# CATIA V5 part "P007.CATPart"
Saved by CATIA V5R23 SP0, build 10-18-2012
Part number: P007
Definition: Vis HC M5x10.1
Description: Vis ISO10642 F HC M5x10.1
Bounding box of the stored display mesh (mm): x -10.29 to 0, y -5.598 to 5.598, z -5.598 to 5.598
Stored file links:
  C:\wamp\www\COURS\CONCEPTION GMP1\TITRE 02-SEMESTRE 2\03-TP7-PRESSE MECANIQUE\eleve\P007.CATPart
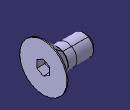
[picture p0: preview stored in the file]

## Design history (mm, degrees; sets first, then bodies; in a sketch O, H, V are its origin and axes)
Parameters
  Material = "St"
  d_dia_max = 5 mm
  l_length_nom = 10 mm
  b_ref = 22
  l_length_min = 9.71 mm
  l_length_max = 10.29 mm
  dk_head_dia_max = 11.2 mm
  dk_head_dia_min = 9.43 mm
  ls = 5.5 mm
  k_hed_depth = 3.1 mm
  r = 0.2 mm
  s_across_flats = 3 mm
  t_insert_depth = 1.9 mm
  P_pitch = 0.8 mm
  PartNumber = "Vis ISO10642 F HC M5x10"
Body1 "PartBody" (main body)
  Sketch1 on zx-plane, origin (0, 0, 0), H (-1, 0, 0), V (0, 0, 1)
    line L1 (0, 5.6) -> (0.2667, 5.6)
    point P2 (0.2667, 5.6)
    line L2 (0.2667, 5.6) -> (3.3667, 2.5)
    line L3 (3.3667, 2.5) -> (5.5, 2.5)
    line L4 (5.5, 2.5) -> (5.5, 2.439)
    point P5 (5.5, 2.439)
    line L5 (5.5, 2.439) -> (9.49, 2.439)
    point P6 (9.49, 2.439)
    line L6 (9.49, 2.439) -> (10.29, 1.639)
    axis line L7 (-30, 0) -> (125, 0)
    line L8 (10.29, 1.639) -> (10.29, 0)
    point P10 (10.29, 0)
    line L9 (0, 5.6) -> (0, 0)
    distance L9 P5 = 5.5 {= ls}
    distance L9 L8 = 10.29 {= l_length_max}
    angle L5 L6 = 45
    distance L5 L7 = 2.439 {= d_dia_max /2.05}
    distance L3 L7 = 2.5 {= d_dia_max /2}
    angle L7 L2 = 45
    distance L1 L7 = 5.6 {= dk_head_dia_max /2}
    distance L9 P2 = 0.2667 {= P_pitch /3}
    distance P6 L8 = 0.8 {= P_pitch}
    horizontal: L1 H, L3 H, L5 H, L7 H
    vertical: L4 V, L9 V
    fix: L7
    coincidence: P10 L7
  Shaft1: profile Sketch1, axis Sketch1.L7, angle 360
  Body2
    Sketch2 on face of Shaft1, origin (0, 0, 0), H (0, 1, 0), V (0, 0, 1)
      point P1 (1.5, -0.866)
      point P2 (1.5, 0.866)
      point P3 (0, 1.7321)
      point P4 (-1.5, 0.866)
      point P5 (-1.5, -0.866)
      point P6 (0, -1.7321)
      point P7 (1.5, 0)
      line L1 (1.5, -0.866) -> (1.5, 0.866)
      line L2 (1.5, 0.866) -> (0, 1.7321)
      line L3 (0, 1.7321) -> (-1.5, 0.866)
      line L4 (-1.5, 0.866) -> (-1.5, -0.866)
      line L5 (-1.5, -0.866) -> (0, -1.7321)
      line L6 (0, -1.7321) -> (1.5, -0.866)
      construction line L7 (0, 0) -> (1.5, 0)
      construction circle A1 centre (0, 0) radius 1.7321
      construction arc A2 centre (-1.5, -0.866) radius 1.7321 from (-1.5, 0.866) to (0, -1.7321) cw
      construction arc A3 centre (1.5, 0.866) radius 1.7321 from (0, 1.7321) to (1.5, -0.866) ccw
      point P8 (-1.5, -0.866)
      point P9 (1.5, 0.866)
      distance L1 L4 = 3 {= s_across_flats}
      horizontal: L7 H
      coincidence: A1 P1, A1 P2, A1 P3, A1 P4, A1 P5, A1 P6, A2 P4, A2 P6, A2 O, P8 P5, A3 P3, A3 P1, A3 O, P9 P2
      midpoint: P7 L1
    Pad1: profile Sketch2, direction (-1, 0, 0), length 20
    Body3
      Sketch3 on zx-plane, origin (0, 0, 0), H (-1, 0, 0), V (0, 0, 1)
        line L1 (0, 0) -> (0, 1.7321)
        line L2 (0, 1.7321) -> (1.9, 1.7321)
        point P2 (1.9, 1.7321)
        line L3 (1.9, 1.7321) -> (2.9, 0)
        point P3 (2.9, 0)
        axis line L4 (-13.9938, 0) -> (46.4324, 0)
        reference projected line E1 (0, 1.7321) -> (20, 1.7321) from edge [face of Pad1 | face of Pad1]
        angle L3 L4 = 60
        distance L1 P2 = 1.9 {= t_insert_depth}
        vertical: L1 V
        horizontal: L2 H, L4 H
        fix: L4
        coincidence: L2 E1, P3 L4
      Shaft2: profile Sketch3, axis Sketch3.L4, angle 360
    Intersect1: tool Body3
  Remove1: tool Body2
  Fillet1: radius 0.2 {= r}, on edge [face of Shaft1 | face of Shaft1]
